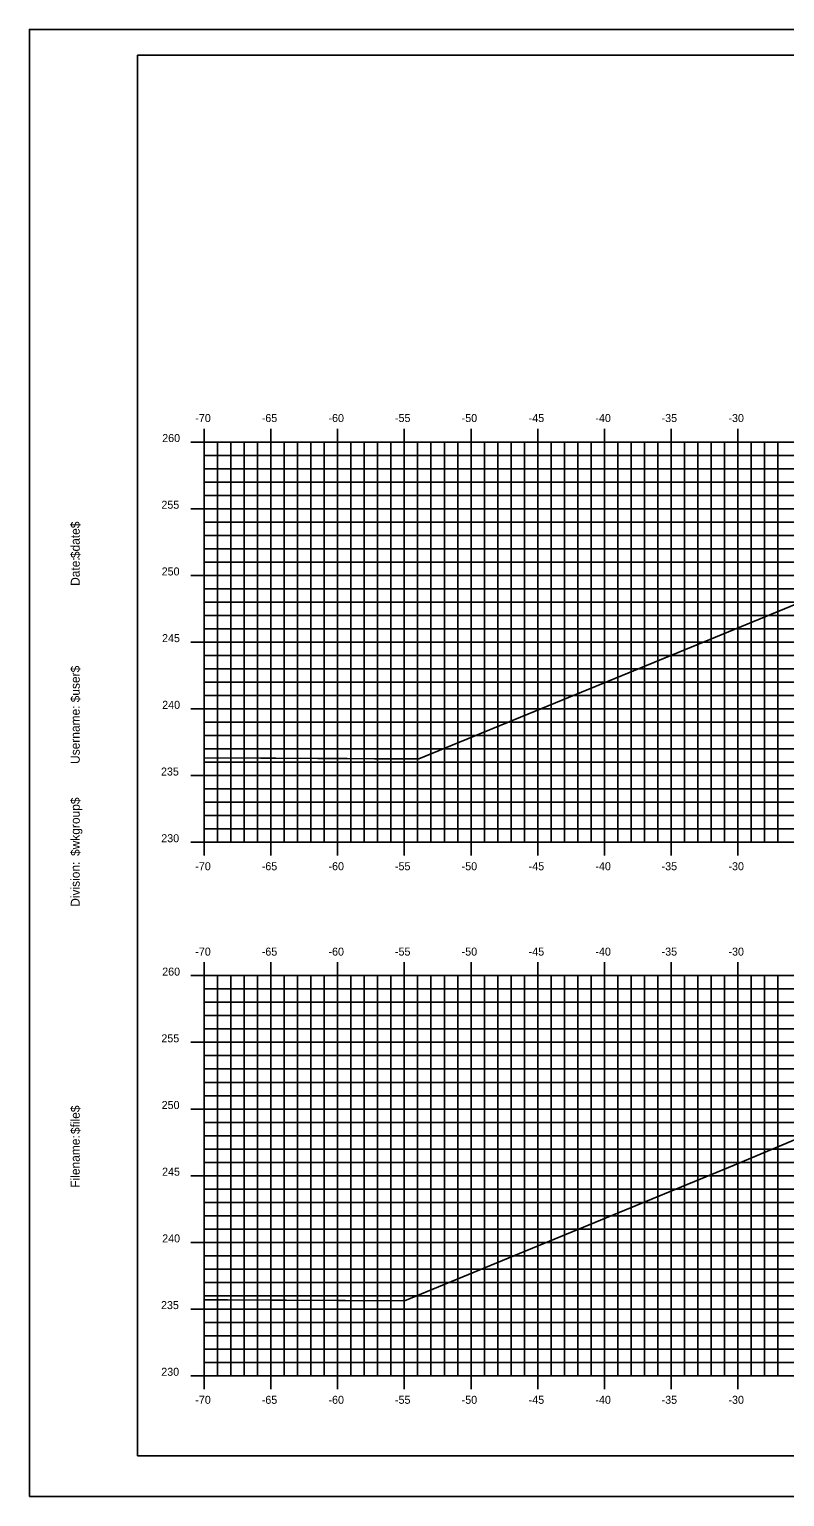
# Model space of a CAD drawing. Extents: x -22 to 1480, y -1511 to 8.
# Drawn here: x 1213.8 to 1270.4, y -1511.4 to -1401.4 of the extents above; entities that cross this region are included whole.
import ezdxf

# ---------------------------------------------------------------- set-up
doc = ezdxf.new("R2010")
doc.units = 0
for name, color, linetype in [('BORDER', 7, 'Continuous'), ('H_V ANNOTATION', 7, 'Continuous'), ('MAJOR', 7, 'Continuous'), ('MINOR', 7, 'Continuous'), ('PLOT BOUNDARY', 7, 'Continuous'), ('S_Roadway_Centerline', 7, 'Continuous')]:
    doc.layers.add(name, color=color, linetype=linetype)

msp = doc.modelspace()

# ---------------------------------------------------------------- linework, layer by layer
at = {"layer": 'BORDER'}
for p, q in [((1381.94, -1403.33), (1221.94, -1403.33)), ((1221.94, -1403.33), (1221.94, -1508.33)), ((1221.94, -1508.33), (1381.94, -1508.33))]:
    msp.add_line(p, q, dxfattribs=at)
at = {"layer": 'MAJOR'}
for p, q in [((1226.94, -1431.33), (1226.94, -1432.33)), ((1231.94, -1431.33), (1231.94, -1432.33)), ((1236.94, -1431.33), (1236.94, -1432.33)), ((1241.94, -1431.33), (1241.94, -1432.33)), ((1246.94, -1431.33), (1246.94, -1432.33)), ((1251.94, -1431.33), (1251.94, -1432.33)), ((1256.94, -1431.33), (1256.94, -1432.33)), ((1261.94, -1431.33), (1261.94, -1432.33)), ((1266.94, -1431.33), (1266.94, -1432.33)), ((1225.94, -1432.33), (1226.94, -1432.33)), ((1226.94, -1432.33), (1366.94, -1432.33)), ((1226.94, -1462.33), (1226.94, -1432.33)), ((1226.94, -1462.33), (1226.94, -1432.33)), ((1226.94, -1432.33), (1366.94, -1432.33)), ((1231.94, -1462.33), (1231.94, -1432.33)), ((1236.94, -1462.33), (1236.94, -1432.33)), ((1241.94, -1462.33), (1241.94, -1432.33)), ((1246.94, -1462.33), (1246.94, -1432.33)), ((1251.94, -1462.33), (1251.94, -1432.33)), ((1256.94, -1462.33), (1256.94, -1432.33)), ((1261.94, -1462.33), (1261.94, -1432.33)), ((1266.94, -1462.33), (1266.94, -1432.33)), ((1225.94, -1437.33), (1226.94, -1437.33)), ((1226.94, -1437.33), (1366.94, -1437.33)), ((1225.94, -1442.33), (1226.94, -1442.33)), ((1226.94, -1442.33), (1366.94, -1442.33)), ((1225.94, -1447.33), (1226.94, -1447.33)), ((1226.94, -1447.33), (1366.94, -1447.33)), ((1225.94, -1452.33), (1226.94, -1452.33)), ((1226.94, -1452.33), (1366.94, -1452.33)), ((1225.94, -1457.33), (1226.94, -1457.33)), ((1226.94, -1457.33), (1366.94, -1457.33)), ((1225.94, -1462.33), (1226.94, -1462.33)), ((1226.94, -1462.33), (1366.94, -1462.33)), ((1226.94, -1462.33), (1366.94, -1462.33)), ((1226.94, -1463.33), (1226.94, -1462.33)), ((1231.94, -1463.33), (1231.94, -1462.33)), ((1236.94, -1463.33), (1236.94, -1462.33)), ((1241.94, -1463.33), (1241.94, -1462.33)), ((1246.94, -1463.33), (1246.94, -1462.33)), ((1251.94, -1463.33), (1251.94, -1462.33)), ((1256.94, -1463.33), (1256.94, -1462.33)), ((1261.94, -1463.33), (1261.94, -1462.33)), ((1266.94, -1463.33), (1266.94, -1462.33)), ((1226.94, -1471.33), (1226.94, -1472.33)), ((1231.94, -1471.33), (1231.94, -1472.33)), ((1236.94, -1471.33), (1236.94, -1472.33)), ((1241.94, -1471.33), (1241.94, -1472.33)), ((1246.94, -1471.33), (1246.94, -1472.33)), ((1251.94, -1471.33), (1251.94, -1472.33)), ((1256.94, -1471.33), (1256.94, -1472.33)), ((1261.94, -1471.33), (1261.94, -1472.33)), ((1266.94, -1471.33), (1266.94, -1472.33)), ((1225.94, -1472.33), (1226.94, -1472.33)), ((1226.94, -1472.33), (1366.94, -1472.33)), ((1226.94, -1502.33), (1226.94, -1472.33)), ((1226.94, -1502.33), (1226.94, -1472.33)), ((1226.94, -1472.33), (1366.94, -1472.33)), ((1231.94, -1502.33), (1231.94, -1472.33)), ((1236.94, -1502.33), (1236.94, -1472.33)), ((1241.94, -1502.33), (1241.94, -1472.33)), ((1246.94, -1502.33), (1246.94, -1472.33)), ((1251.94, -1502.33), (1251.94, -1472.33)), ((1256.94, -1502.33), (1256.94, -1472.33)), ((1261.94, -1502.33), (1261.94, -1472.33)), ((1266.94, -1502.33), (1266.94, -1472.33)), ((1225.94, -1477.33), (1226.94, -1477.33)), ((1226.94, -1477.33), (1366.94, -1477.33)), ((1225.94, -1482.33), (1226.94, -1482.33)), ((1226.94, -1482.33), (1366.94, -1482.33)), ((1225.94, -1487.33), (1226.94, -1487.33)), ((1226.94, -1487.33), (1366.94, -1487.33)), ((1225.94, -1492.33), (1226.94, -1492.33)), ((1226.94, -1492.33), (1366.94, -1492.33)), ((1225.94, -1497.33), (1226.94, -1497.33)), ((1226.94, -1497.33), (1366.94, -1497.33)), ((1225.94, -1502.33), (1226.94, -1502.33)), ((1226.94, -1502.33), (1366.94, -1502.33)), ((1226.94, -1502.33), (1366.94, -1502.33)), ((1226.94, -1503.33), (1226.94, -1502.33)), ((1231.94, -1503.33), (1231.94, -1502.33)), ((1236.94, -1503.33), (1236.94, -1502.33)), ((1241.94, -1503.33), (1241.94, -1502.33)), ((1246.94, -1503.33), (1246.94, -1502.33)), ((1251.94, -1503.33), (1251.94, -1502.33)), ((1256.94, -1503.33), (1256.94, -1502.33)), ((1261.94, -1503.33), (1261.94, -1502.33)), ((1266.94, -1503.33), (1266.94, -1502.33))]:
    msp.add_line(p, q, dxfattribs=at)
at = {"layer": 'MINOR'}
for p, q in [((1227.94, -1462.33), (1227.94, -1432.33)), ((1228.94, -1462.33), (1228.94, -1432.33)), ((1229.94, -1462.33), (1229.94, -1432.33)), ((1230.94, -1462.33), (1230.94, -1432.33)), ((1232.94, -1462.33), (1232.94, -1432.33)), ((1233.94, -1462.33), (1233.94, -1432.33)), ((1234.94, -1462.33), (1234.94, -1432.33)), ((1235.94, -1462.33), (1235.94, -1432.33)), ((1237.94, -1462.33), (1237.94, -1432.33)), ((1238.94, -1462.33), (1238.94, -1432.33)), ((1239.94, -1462.33), (1239.94, -1432.33)), ((1240.94, -1462.33), (1240.94, -1432.33)), ((1242.94, -1462.33), (1242.94, -1432.33)), ((1243.94, -1462.33), (1243.94, -1432.33)), ((1244.94, -1462.33), (1244.94, -1432.33)), ((1245.94, -1462.33), (1245.94, -1432.33)), ((1247.94, -1462.33), (1247.94, -1432.33)), ((1248.94, -1462.33), (1248.94, -1432.33)), ((1249.94, -1462.33), (1249.94, -1432.33)), ((1250.94, -1462.33), (1250.94, -1432.33)), ((1252.94, -1462.33), (1252.94, -1432.33)), ((1253.94, -1462.33), (1253.94, -1432.33)), ((1254.94, -1462.33), (1254.94, -1432.33)), ((1255.94, -1462.33), (1255.94, -1432.33)), ((1257.94, -1462.33), (1257.94, -1432.33)), ((1258.94, -1462.33), (1258.94, -1432.33)), ((1259.94, -1462.33), (1259.94, -1432.33)), ((1260.94, -1462.33), (1260.94, -1432.33)), ((1262.94, -1462.33), (1262.94, -1432.33)), ((1263.94, -1462.33), (1263.94, -1432.33)), ((1264.94, -1462.33), (1264.94, -1432.33)), ((1265.94, -1462.33), (1265.94, -1432.33)), ((1267.94, -1462.33), (1267.94, -1432.33)), ((1268.94, -1462.33), (1268.94, -1432.33)), ((1269.94, -1462.33), (1269.94, -1432.33)), ((1226.94, -1433.33), (1366.94, -1433.33)), ((1226.94, -1433.33), (1227.94, -1433.33)), ((1226.94, -1434.33), (1366.94, -1434.33)), ((1226.94, -1434.33), (1227.94, -1434.33)), ((1226.94, -1435.33), (1366.94, -1435.33)), ((1226.94, -1435.33), (1227.94, -1435.33)), ((1226.94, -1436.33), (1366.94, -1436.33)), ((1226.94, -1436.33), (1227.94, -1436.33)), ((1226.94, -1438.33), (1366.94, -1438.33)), ((1226.94, -1438.33), (1227.94, -1438.33)), ((1226.94, -1439.33), (1366.94, -1439.33)), ((1226.94, -1439.33), (1227.94, -1439.33)), ((1226.94, -1440.33), (1366.94, -1440.33)), ((1226.94, -1440.33), (1227.94, -1440.33)), ((1226.94, -1441.33), (1366.94, -1441.33)), ((1226.94, -1441.33), (1227.94, -1441.33)), ((1226.94, -1443.33), (1366.94, -1443.33)), ((1226.94, -1443.33), (1227.94, -1443.33)), ((1226.94, -1444.33), (1366.94, -1444.33)), ((1226.94, -1444.33), (1227.94, -1444.33)), ((1226.94, -1445.33), (1366.94, -1445.33)), ((1226.94, -1445.33), (1227.94, -1445.33)), ((1226.94, -1446.33), (1366.94, -1446.33)), ((1226.94, -1446.33), (1227.94, -1446.33)), ((1226.94, -1448.33), (1366.94, -1448.33)), ((1226.94, -1448.33), (1227.94, -1448.33)), ((1226.94, -1449.33), (1366.94, -1449.33)), ((1226.94, -1449.33), (1227.94, -1449.33)), ((1226.94, -1450.33), (1366.94, -1450.33)), ((1226.94, -1450.33), (1227.94, -1450.33)), ((1226.94, -1451.33), (1366.94, -1451.33)), ((1226.94, -1451.33), (1227.94, -1451.33)), ((1226.94, -1453.33), (1366.94, -1453.33)), ((1226.94, -1453.33), (1227.94, -1453.33)), ((1226.94, -1454.33), (1366.94, -1454.33)), ((1226.94, -1454.33), (1227.94, -1454.33)), ((1226.94, -1455.33), (1366.94, -1455.33)), ((1226.94, -1455.33), (1227.94, -1455.33)), ((1226.94, -1456.33), (1366.94, -1456.33)), ((1226.94, -1456.33), (1227.94, -1456.33)), ((1226.94, -1458.33), (1366.94, -1458.33)), ((1226.94, -1458.33), (1227.94, -1458.33)), ((1226.94, -1459.33), (1366.94, -1459.33)), ((1226.94, -1459.33), (1227.94, -1459.33)), ((1226.94, -1460.33), (1366.94, -1460.33)), ((1226.94, -1460.33), (1227.94, -1460.33)), ((1226.94, -1461.33), (1366.94, -1461.33)), ((1226.94, -1461.33), (1227.94, -1461.33)), ((1227.94, -1502.33), (1227.94, -1472.33)), ((1228.94, -1502.33), (1228.94, -1472.33)), ((1229.94, -1502.33), (1229.94, -1472.33)), ((1230.94, -1502.33), (1230.94, -1472.33)), ((1232.94, -1502.33), (1232.94, -1472.33)), ((1233.94, -1502.33), (1233.94, -1472.33)), ((1234.94, -1502.33), (1234.94, -1472.33)), ((1235.94, -1502.33), (1235.94, -1472.33)), ((1237.94, -1502.33), (1237.94, -1472.33)), ((1238.94, -1502.33), (1238.94, -1472.33)), ((1239.94, -1502.33), (1239.94, -1472.33)), ((1240.94, -1502.33), (1240.94, -1472.33)), ((1242.94, -1502.33), (1242.94, -1472.33)), ((1243.94, -1502.33), (1243.94, -1472.33)), ((1244.94, -1502.33), (1244.94, -1472.33)), ((1245.94, -1502.33), (1245.94, -1472.33)), ((1247.94, -1502.33), (1247.94, -1472.33)), ((1248.94, -1502.33), (1248.94, -1472.33)), ((1249.94, -1502.33), (1249.94, -1472.33)), ((1250.94, -1502.33), (1250.94, -1472.33)), ((1252.94, -1502.33), (1252.94, -1472.33)), ((1253.94, -1502.33), (1253.94, -1472.33)), ((1254.94, -1502.33), (1254.94, -1472.33)), ((1255.94, -1502.33), (1255.94, -1472.33)), ((1257.94, -1502.33), (1257.94, -1472.33)), ((1258.94, -1502.33), (1258.94, -1472.33)), ((1259.94, -1502.33), (1259.94, -1472.33)), ((1260.94, -1502.33), (1260.94, -1472.33)), ((1262.94, -1502.33), (1262.94, -1472.33)), ((1263.94, -1502.33), (1263.94, -1472.33)), ((1264.94, -1502.33), (1264.94, -1472.33)), ((1265.94, -1502.33), (1265.94, -1472.33)), ((1267.94, -1502.33), (1267.94, -1472.33)), ((1268.94, -1502.33), (1268.94, -1472.33)), ((1269.94, -1502.33), (1269.94, -1472.33)), ((1226.94, -1473.33), (1366.94, -1473.33)), ((1226.94, -1473.33), (1227.94, -1473.33)), ((1226.94, -1474.33), (1366.94, -1474.33)), ((1226.94, -1474.33), (1227.94, -1474.33)), ((1226.94, -1475.33), (1366.94, -1475.33)), ((1226.94, -1475.33), (1227.94, -1475.33)), ((1226.94, -1476.33), (1366.94, -1476.33)), ((1226.94, -1476.33), (1227.94, -1476.33)), ((1226.94, -1478.33), (1366.94, -1478.33)), ((1226.94, -1478.33), (1227.94, -1478.33)), ((1226.94, -1479.33), (1366.94, -1479.33)), ((1226.94, -1479.33), (1227.94, -1479.33)), ((1226.94, -1480.33), (1366.94, -1480.33)), ((1226.94, -1480.33), (1227.94, -1480.33)), ((1226.94, -1481.33), (1366.94, -1481.33)), ((1226.94, -1481.33), (1227.94, -1481.33)), ((1226.94, -1483.33), (1366.94, -1483.33)), ((1226.94, -1483.33), (1227.94, -1483.33)), ((1226.94, -1484.33), (1366.94, -1484.33)), ((1226.94, -1484.33), (1227.94, -1484.33)), ((1226.94, -1485.33), (1366.94, -1485.33)), ((1226.94, -1485.33), (1227.94, -1485.33)), ((1226.94, -1486.33), (1366.94, -1486.33)), ((1226.94, -1486.33), (1227.94, -1486.33)), ((1226.94, -1488.33), (1366.94, -1488.33)), ((1226.94, -1488.33), (1227.94, -1488.33)), ((1226.94, -1489.33), (1366.94, -1489.33)), ((1226.94, -1489.33), (1227.94, -1489.33)), ((1226.94, -1490.33), (1366.94, -1490.33)), ((1226.94, -1490.33), (1227.94, -1490.33)), ((1226.94, -1491.33), (1366.94, -1491.33)), ((1226.94, -1491.33), (1227.94, -1491.33)), ((1226.94, -1493.33), (1366.94, -1493.33)), ((1226.94, -1493.33), (1227.94, -1493.33)), ((1226.94, -1494.33), (1366.94, -1494.33)), ((1226.94, -1494.33), (1227.94, -1494.33)), ((1226.94, -1495.33), (1366.94, -1495.33)), ((1226.94, -1495.33), (1227.94, -1495.33)), ((1226.94, -1496.33), (1366.94, -1496.33)), ((1226.94, -1496.33), (1227.94, -1496.33)), ((1226.94, -1498.33), (1366.94, -1498.33)), ((1226.94, -1498.33), (1227.94, -1498.33)), ((1226.94, -1499.33), (1366.94, -1499.33)), ((1226.94, -1499.33), (1227.94, -1499.33)), ((1226.94, -1500.33), (1366.94, -1500.33)), ((1226.94, -1500.33), (1227.94, -1500.33)), ((1226.94, -1501.33), (1366.94, -1501.33)), ((1226.94, -1501.33), (1227.94, -1501.33))]:
    msp.add_line(p, q, dxfattribs=at)
at = {"layer": 'PLOT BOUNDARY'}
msp.add_lwpolyline([(1213.85, -1511.39), (1383.85, -1511.39), (1383.85, -1401.39), (1213.85, -1401.39)], close=True, dxfattribs=at)
at = {"layer": 'S_Roadway_Centerline'}
for points in [[(1226.94, -1456.01), (1239.7, -1456.07), (1243.03, -1456.08), (1257.29, -1450.22), (1275.59, -1442.71)], [(1226.94, -1456.01), (1243.03, -1456.08), (1257.29, -1450.22), (1275.59, -1442.71)], [(1226.94, -1496.64), (1228.7, -1496.64), (1241.96, -1496.7), (1266.65, -1486.54), (1275.05, -1483.02)], [(1226.94, -1496.64), (1241.96, -1496.7), (1266.65, -1486.54), (1275.05, -1483.02)]]:
    msp.add_lwpolyline(points, dxfattribs=at)

# ---------------------------------------------------------------- texts
at = {"layer": 'BORDER'}
for s, p in [('$date$', (1217.62, -1441.03)), ('Date:', (1217.62, -1443.11)), ('$user$', (1217.62, -1451.84)), ('Username:', (1217.62, -1456.46)), ('$wkgroup$', (1217.62, -1463.36)), ('Division:', (1217.62, -1467.17)), ('$file$', (1217.62, -1484.21)), ('Filename:', (1217.62, -1488.23))]:
    msp.add_text(s, height=0.67, rotation=90, dxfattribs=at).set_placement(p)
at = {"layer": 'H_V ANNOTATION'}
for s, p in [('-70', (1226.28, -1430.83)), ('-65', (1231.26, -1430.83)), ('-60', (1236.26, -1430.83)), ('-55', (1241.24, -1430.83)), ('-50', (1246.24, -1430.83)), ('-45', (1251.26, -1430.83)), ('-40', (1256.26, -1430.83)), ('-35', (1261.22, -1430.83)), ('-30', (1266.23, -1430.83)), ('260', (1223.8, -1432.33)), ('255', (1223.74, -1437.33)), ('250', (1223.76, -1442.33)), ('245', (1223.79, -1447.33)), ('240', (1223.8, -1452.33)), ('235', (1223.71, -1457.33)), ('230', (1223.73, -1462.33)), ('-70', (1226.28, -1464.43)), ('-65', (1231.26, -1464.43)), ('-60', (1236.26, -1464.43)), ('-55', (1241.24, -1464.43)), ('-50', (1246.24, -1464.43)), ('-45', (1251.26, -1464.43)), ('-40', (1256.26, -1464.43)), ('-35', (1261.22, -1464.43)), ('-30', (1266.23, -1464.43)), ('-70', (1226.28, -1470.83)), ('-65', (1231.26, -1470.83)), ('-60', (1236.26, -1470.83)), ('-55', (1241.24, -1470.83)), ('-50', (1246.24, -1470.83)), ('-45', (1251.26, -1470.83)), ('-40', (1256.26, -1470.83)), ('-35', (1261.22, -1470.83)), ('-30', (1266.23, -1470.83)), ('260', (1223.8, -1472.33)), ('255', (1223.74, -1477.33)), ('250', (1223.76, -1482.33)), ('245', (1223.79, -1487.33)), ('240', (1223.8, -1492.33)), ('235', (1223.71, -1497.33)), ('230', (1223.73, -1502.33)), ('-70', (1226.28, -1504.43)), ('-65', (1231.26, -1504.43)), ('-60', (1236.26, -1504.43)), ('-55', (1241.24, -1504.43)), ('-50', (1246.24, -1504.43)), ('-45', (1251.26, -1504.43)), ('-40', (1256.26, -1504.43)), ('-35', (1261.22, -1504.43)), ('-30', (1266.23, -1504.43))]:
    msp.add_text(s, height=0.6, dxfattribs=at).set_placement(p)

doc.saveas('drawing.dxf')
